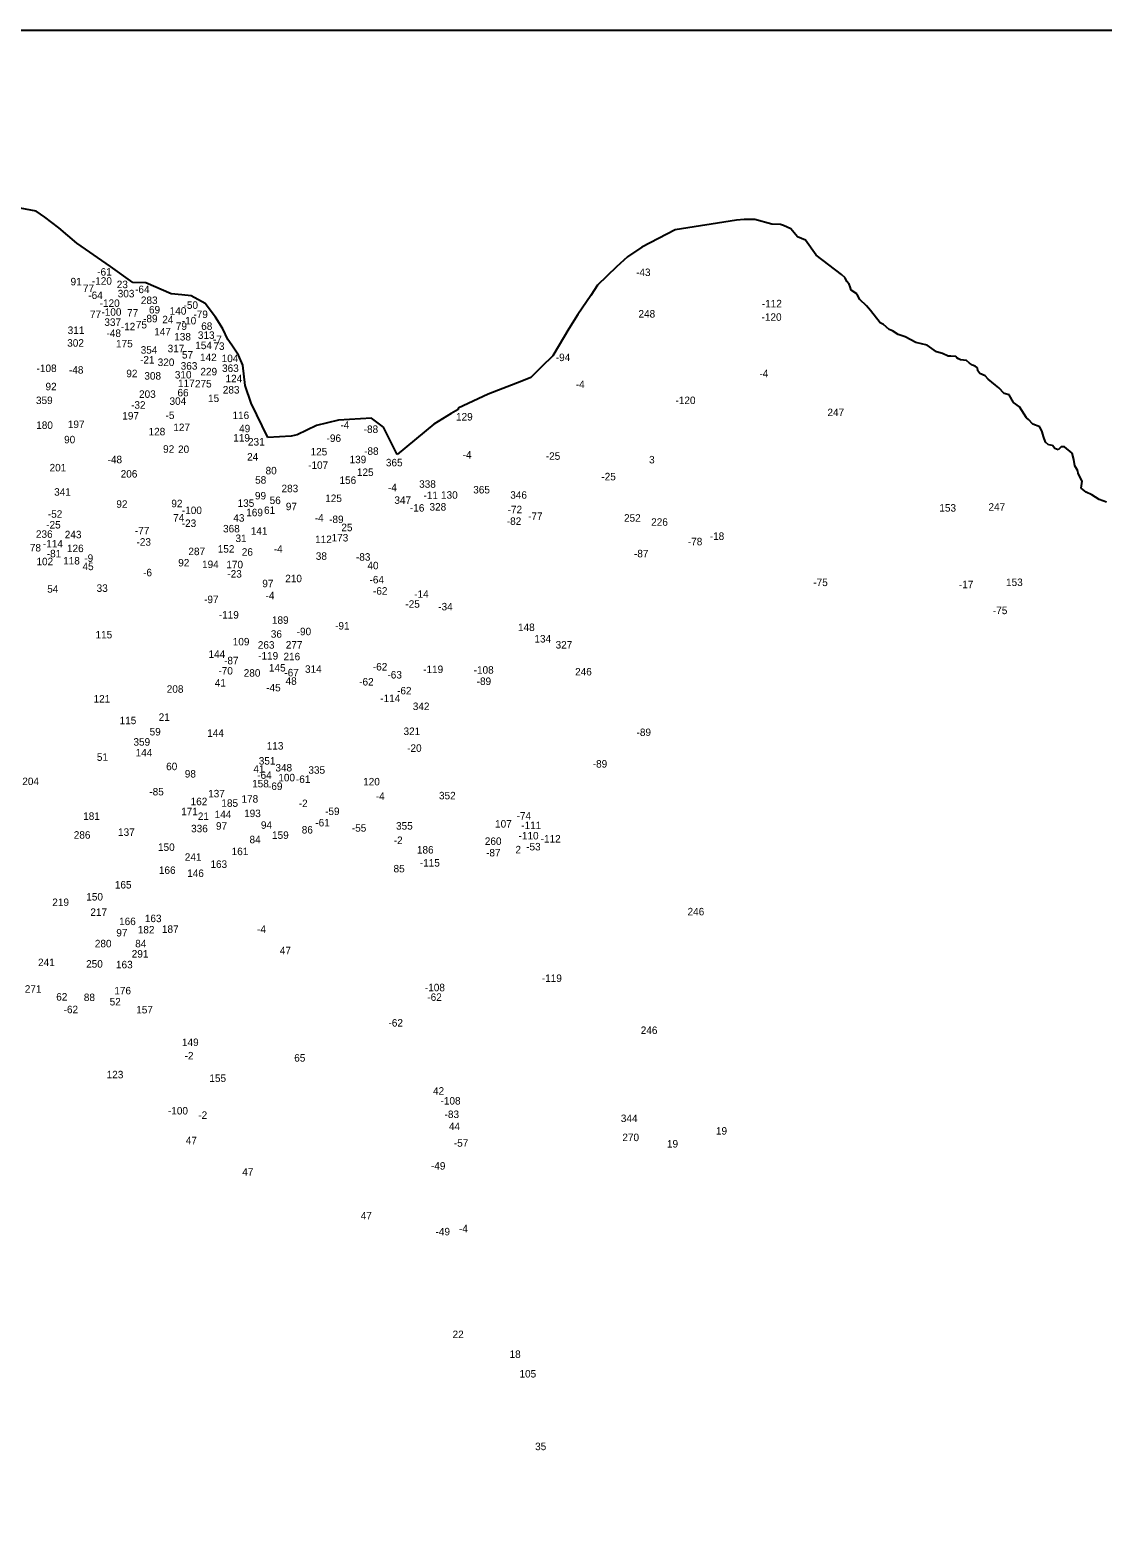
# Model space of a CAD drawing. Extents: x -780246 to -774760, y -968897 to -964868.
# Drawn here: x -778940 to -777505, y -966883 to -964868 of the extents above; entities that cross this region are included whole.
import ezdxf

# ---------------------------------------------------------------- set-up
doc = ezdxf.new("R2010")
doc.units = 0
doc.layers.add('Vrstva 13', color=7, linetype='Continuous')
doc.layers.add('Vrstva 15', color=7, linetype='Continuous')

msp = doc.modelspace()

# ---------------------------------------------------------------- linework, layer by layer
at = {"layer": 'Vrstva 13'}
for p, q in [((-778931.37, -965109.54), (-778959.99, -965104.36)), ((-778920.05, -965117.58), (-778931.37, -965109.54)), ((-778901.29, -965131.68), (-778920.05, -965117.58)), ((-777994.74, -965121.37), (-778077.17, -965134.45)), ((-777984.77, -965120.64), (-777994.74, -965121.37)), ((-777970.46, -965120.49), (-777984.77, -965120.64)), ((-777947.87, -965126.74), (-777970.46, -965120.49)), ((-778876.9, -965152.21), (-778901.29, -965131.68)), ((-778077.17, -965134.45), (-778121.63, -965157.53)), ((-777935.93, -965127.44), (-777947.87, -965126.74)), ((-777932.02, -965128.9), (-777935.93, -965127.44)), ((-777922.28, -965133.21), (-777932.02, -965128.9)), ((-777913.44, -965143.83), (-777922.28, -965133.21)), ((-778832.29, -965183.33), (-778876.9, -965152.21)), ((-778121.63, -965157.53), (-778140.83, -965170.82)), ((-777902.7, -965148.47), (-777913.44, -965143.83)), ((-777888.43, -965168.41), (-777902.7, -965148.47)), ((-778802.2, -965205.02), (-778832.29, -965183.33)), ((-778140.83, -965170.82), (-778155.55, -965183.82)), ((-777854.72, -965194.26), (-777888.43, -965168.41)), ((-778155.55, -965183.82), (-778180.7, -965208.72)), ((-777849.77, -965198.81), (-777854.72, -965194.26)), ((-777847.27, -965203.76), (-777849.77, -965198.81)), ((-777844.31, -965207.37), (-777847.27, -965203.76)), ((-778785.02, -965205.29), (-778802.2, -965205.02)), ((-778750.81, -965220.01), (-778785.02, -965205.29)), ((-778736.68, -965221.29), (-778750.81, -965220.01)), ((-778724.02, -965222.85), (-778736.68, -965221.29)), ((-778705.55, -965232.93), (-778724.02, -965222.85)), ((-778189.61, -965222.16), (-778207.13, -965247.73)), ((-778180.7, -965208.72), (-778189.61, -965222.16)), ((-777842.79, -965210.6), (-777844.31, -965207.37)), ((-777841.47, -965215.12), (-777842.79, -965210.6)), ((-777833.9, -965220.04), (-777841.47, -965215.12)), ((-777830.05, -965227.46), (-777833.9, -965220.04)), ((-778691.6, -965251.34), (-778705.55, -965232.93)), ((-777821, -965236.09), (-777830.05, -965227.46)), ((-777815.83, -965242.59), (-777821, -965236.09)), ((-777802.97, -965258.8), (-777815.83, -965242.59)), ((-778681.67, -965266.97), (-778691.6, -965251.34)), ((-778207.13, -965247.73), (-778219.21, -965266.86)), ((-777798.31, -965261.25), (-777802.97, -965258.8)), ((-777790.64, -965267.83), (-777798.31, -965261.25)), ((-778675.25, -965281.07), (-778681.67, -965266.97)), ((-778669.7, -965288.59), (-778675.25, -965281.07)), ((-778219.21, -965266.86), (-778240.53, -965303.01)), ((-777786.42, -965269.76), (-777790.64, -965267.83)), ((-777778.78, -965274.35), (-777786.42, -965269.76)), ((-777769.51, -965277.78), (-777778.78, -965274.35)), ((-777755.12, -965285.16), (-777769.51, -965277.78)), ((-778660.79, -965302.32), (-778669.7, -965288.59)), ((-778655.03, -965315.25), (-778660.79, -965302.32)), ((-778240.53, -965303.01), (-778255.82, -965317.62)), ((-777740.05, -965288.81), (-777755.12, -965285.16)), ((-777727.39, -965297.64), (-777740.05, -965288.81)), ((-777719.54, -965299.68), (-777727.39, -965297.64)), ((-777712.06, -965303.41), (-777719.54, -965299.68)), ((-777708.3, -965303.26), (-777712.06, -965303.41)), ((-777701.67, -965303.79), (-777708.3, -965303.26)), ((-777700.1, -965305.66), (-777701.67, -965303.79)), ((-778652.03, -965342.86), (-778655.03, -965315.25)), ((-778255.82, -965317.62), (-778270.13, -965331.93)), ((-777698.18, -965307.17), (-777700.1, -965305.66)), ((-777695.54, -965308.41), (-777698.18, -965307.17)), ((-777687.4, -965309.41), (-777695.54, -965308.41)), ((-777683.26, -965312.92), (-777687.4, -965309.41)), ((-777679.2, -965315.64), (-777683.26, -965312.92)), ((-777675.61, -965316.96), (-777679.2, -965315.64)), ((-777672.73, -965318.89), (-777675.61, -965316.96)), ((-777672, -965323.09), (-777672.73, -965318.89)), ((-777669.47, -965326.41), (-777672, -965323.09)), ((-778644.07, -965366.38), (-778652.03, -965342.86)), ((-778281.79, -965337.04), (-778327.17, -965354.2)), ((-778270.13, -965331.93), (-778281.79, -965337.04)), ((-777662.57, -965329.61), (-777669.47, -965326.41)), ((-777658.47, -965334.07), (-777662.57, -965329.61)), ((-777648.59, -965342.14), (-777658.47, -965334.07)), ((-777644.07, -965345.63), (-777648.59, -965342.14)), ((-778327.17, -965354.2), (-778367.26, -965373.05)), ((-777636.83, -965353.21), (-777644.07, -965345.63)), ((-777630.11, -965355.22), (-777636.83, -965353.21)), ((-777624.4, -965365.59), (-777630.11, -965355.22)), ((-778621.66, -965412.4), (-778644.07, -965366.38)), ((-778376.46, -965380.28), (-778399.58, -965394.48)), ((-778366.97, -965374.95), (-778376.46, -965380.28)), ((-778367.26, -965373.05), (-778366.97, -965374.95)), ((-777616.42, -965370.99), (-777624.4, -965365.59)), ((-777607.21, -965386.09), (-777616.42, -965370.99)), ((-778556.75, -965396.33), (-778582.67, -965408.67)), ((-778527.1, -965388.8), (-778556.75, -965396.33)), ((-778483.22, -965386.17), (-778527.1, -965388.8)), ((-778466.94, -965398.59), (-778483.22, -965386.17)), ((-778448.53, -965434.83), (-778466.94, -965398.59)), ((-778399.58, -965394.48), (-778448.53, -965434.83)), ((-777604.23, -965387.99), (-777607.21, -965386.09)), ((-777598.44, -965394.16), (-777604.23, -965387.99)), ((-777589.29, -965398.05), (-777598.44, -965394.16)), ((-777586.08, -965404.48), (-777589.29, -965398.05)), ((-777584.51, -965410.9), (-777586.08, -965404.48)), ((-778590.63, -965410.54), (-778621.66, -965412.4)), ((-778582.67, -965408.67), (-778590.63, -965410.54)), ((-777581.92, -965418.28), (-777584.51, -965410.9)), ((-777577.54, -965421.93), (-777581.92, -965418.28)), ((-777572.4, -965422.84), (-777577.54, -965421.93)), ((-777569.22, -965426.75), (-777572.4, -965422.84)), ((-777560.79, -965424.46), (-777564.77, -965428.86)), ((-777556.34, -965424.53), (-777560.79, -965424.46)), ((-777546.19, -965433.31), (-777556.34, -965424.53)), ((-777564.77, -965428.86), (-777569.22, -965426.75)), ((-777543.72, -965441.54), (-777546.19, -965433.31)), ((-777542.51, -965450.22), (-777543.72, -965441.54)), ((-777538.68, -965456.8), (-777542.51, -965450.22)), ((-777537.8, -965460.38), (-777538.68, -965456.8)), ((-777532.55, -965470.45), (-777537.8, -965460.38)), ((-777533.87, -965480), (-777532.55, -965470.45)), ((-777527.52, -965485.4), (-777533.87, -965480)), ((-777519.57, -965489.05), (-777527.52, -965485.4)), ((-777509.86, -965495.26), (-777519.57, -965489.05)), ((-777500.15, -965498.69), (-777509.86, -965495.26))]:
    msp.add_line(p, q, dxfattribs=at)
msp.add_lwpolyline([(-780246.31, -964867.52), (-774759.73, -964867.52), (-774759.73, -968897.03), (-780246.31, -968897.03)], close=True, dxfattribs=at)

# ---------------------------------------------------------------- texts
at = {"layer": 'Vrstva 15'}
for s, p in [('91', (-778885.494, -965208.7)), ('-120', (-778856.965, -965207.86)), ('-61', (-778849.858, -965195.7)), ('23', (-778823.726, -965212.51)), ('-43', (-778129.256, -965196.3)), ('77', (-778868.934, -965217.67)), ('-64', (-778861.77, -965227.05)), ('303', (-778822.416, -965224.76)), ('-64', (-778799.24, -965219.13)), ('283', (-778791.456, -965233.7)), ('77', (-778859.564, -965252.61)), ('-120', (-778846.565, -965237.6)), ('-100', (-778844.214, -965249.38)), ('77', (-778809.884, -965250.54)), ('69', (-778780.644, -965246.32)), ('140', (-778752.937, -965247.92)), ('-50', (-778734.39, -965240.15)), ('-79', (-778721.192, -965252.46)), ('248', (-778126.012, -965251.83)), ('-112', (-777961.039, -965238.14)), ('311', (-778889.346, -965273.77)), ('337', (-778840.316, -965262.93)), ('-12', (-778818.314, -965268.79)), ('75', (-778798.175, -965266.38)), ('-89', (-778788.504, -965258.17)), ('24', (-778762.822, -965259.48)), ('79', (-778744.708, -965268.38)), ('-10', (-778736.755, -965260.95)), ('68', (-778710.78, -965268.28)), ('-120', (-777961.405, -965256.15)), ('302', (-778889.976, -965290.74)), ('-48', (-778837.406, -965277.72)), ('175', (-778824.69, -965291.66)), ('147', (-778773.606, -965275.72)), ('138', (-778746.871, -965282.46)), ('154', (-778718.777, -965294.03)), ('313', (-778715.231, -965280.3)), ('-7', (-778695.049, -965285.98)), ('-21', (-778792.544, -965313.33)), ('354', (-778791.682, -965300.1)), ('317', (-778755.67, -965298.22)), ('57', (-778736.496, -965306.58)), ('142', (-778712.396, -965310.05)), ('73', (-778694.465, -965295.06)), ('104', (-778683.407, -965311.43)), ('-94', (-778236.6, -965310.04)), ('-108', (-778930.914, -965324.65)), ('-48', (-778887.606, -965326.8)), ('92', (-778810.94, -965331.58)), ('308', (-778786.816, -965334.77)), ('320', (-778768.966, -965316.57)), ('310', (-778746.051, -965333.28)), ('363', (-778738.22, -965321.45)), ('229', (-778711.85, -965329.07)), ('363', (-778682.89, -965324.52)), ('-4', (-777964.306, -965331.58)), ('92', (-778919, -965349.06)), ('117', (-778741.774, -965344.7)), ('275', (-778719.135, -965345.3)), ('283', (-778681.916, -965353.39)), ('124', (-778678.257, -965338.36)), ('-4', (-778209.866, -965346.07)), ('359', (-778931.77, -965367.48)), ('-32', (-778804.58, -965373.68)), ('203', (-778793.906, -965359.16)), ('304', (-778753.182, -965368.52)), ('66', (-778742.514, -965357.23)), ('15', (-778701.631, -965364.8)), ('-120', (-778076.515, -965367.48)), ('197', (-778816.303, -965388.13)), ('-5', (-778758.45, -965387.45)), ('116', (-778668.939, -965387.54)), ('129', (-778370.004, -965389.46)), ('247', (-777873.291, -965383.62)), ('180', (-778931.411, -965400.71)), ('197', (-778889.133, -965399.55)), ('128', (-778781.201, -965409.28)), ('127', (-778748.06, -965403.59)), ('49', (-778660.076, -965405.2)), ('-4', (-778524.616, -965400.51)), ('-88', (-778493.5, -965406.08)), ('90', (-778894.12, -965419.95)), ('92', (-778761.74, -965432.55)), ('20', (-778741.776, -965432.96)), ('119', (-778667.969, -965417.64)), ('231', (-778648.231, -965422.92)), ('-96', (-778543.107, -965418.09)), ('-88', (-778492.91, -965435.38)), ('-48', (-778835.946, -965446.62)), ('24', (-778649.382, -965442.99)), ('-107', (-778567.794, -965454.13)), ('125', (-778564.551, -965436.15)), ('139', (-778512.404, -965446.61)), ('365', (-778463.78, -965450.71)), ('-4', (-778361.186, -965440.36)), ('-25', (-778249.93, -965442.01)), ('3', (-778111.816, -965446.84)), ('201', (-778913.56, -965457.49)), ('206', (-778818.46, -965465.79)), ('58', (-778638.686, -965473.95)), ('80', (-778624.686, -965461.45)), ('156', (-778525.854, -965474.25)), ('125', (-778502.561, -965463.64)), ('-25', (-778175.66, -965469.45)), ('341', (-778907.406, -965489.98)), ('99', (-778638.934, -965494.99)), ('283', (-778603.376, -965485.36)), ('-4', (-778461.056, -965484.01)), ('338', (-778419.336, -965479.41)), ('-11', (-778413.479, -965494.46)), ('130', (-778390.081, -965494.05)), ('365', (-778346.99, -965487.02)), ('346', (-778297.466, -965494.05)), ('92', (-778824.27, -965506.15)), ('92', (-778750.71, -965505.46)), ('-100', (-778736.634, -965514.53)), ('135', (-778662.121, -965504.92)), ('61', (-778626.754, -965514.44)), ('56', (-778619.26, -965501.21)), ('97', (-778597.598, -965509.43)), ('125', (-778544.961, -965498.46)), ('347', (-778452.471, -965500.93)), ('-16', (-778431.638, -965511.26)), ('328', (-778405.476, -965509.94)), ('-72', (-778300.968, -965513.51)), ('153', (-777723.661, -965511.3)), ('247', (-777657.971, -965510.06)), ('-25', (-778918.06, -965533.88)), ('-52', (-778915.86, -965519.49)), ('74', (-778748.301, -965524.54)), ('-23', (-778736.81, -965531.82)), ('43', (-778667.812, -965524.74)), ('169', (-778650.598, -965517.47)), ('-4', (-778558.936, -965524.69)), ('-89', (-778539.734, -965526.6)), ('-82', (-778302.1, -965529.05)), ('-77', (-778273.618, -965522.3)), ('252', (-778145.376, -965524.78)), ('226', (-778109.02, -965530.19)), ('236', (-778931.8, -965546.31)), ('243', (-778893.242, -965546.94)), ('-77', (-778799.438, -965541.67)), ('368', (-778681.55, -965539.08)), ('31', (-778664.971, -965551.96)), ('141', (-778644.491, -965542.15)), ('112', (-778558.476, -965553.36)), ('173', (-778536.43, -965551.21)), ('25', (-778523.356, -965537.49)), ('-78', (-778059.978, -965556.3)), ('-18', (-778030.674, -965549.12)), ('78', (-778939.965, -965564.6)), ('-114', (-778922.495, -965559.26)), ('-81', (-778917.314, -965572.41)), ('126', (-778890.314, -965565.49)), ('-23', (-778797.31, -965556.83)), ('287', (-778727.926, -965569.51)), ('152', (-778688.671, -965566.15)), ('26', (-778656.51, -965570.23)), ('-4', (-778613.776, -965566.29)), ('38', (-778557.516, -965575.74)), ('-83', (-778503.84, -965576.9)), ('-87', (-778132.029, -965572.41)), ('102', (-778931.13, -965583.01)), ('118', (-778895.426, -965582)), ('45', (-778869.502, -965589.56)), ('-9', (-778867.094, -965578.46)), ('92', (-778741.51, -965584.58)), ('194', (-778709.63, -965586.77)), ('170', (-778677.15, -965587.06)), ('40', (-778488.502, -965588.39)), ('-6', (-778788.494, -965597.72)), ('-23', (-778675.82, -965599.52)), ('97', (-778629.088, -965612.44)), ('210', (-778598.391, -965605.75)), ('-64', (-778485.67, -965607.23)), ('-75', (-777892.228, -965610.9)), ('-17', (-777697.524, -965613.69)), ('153', (-777634.471, -965610.78)), ('54', (-778916.722, -965619.7)), ('33', (-778850.666, -965618.59)), ('-97', (-778706.962, -965633.65)), ('-4', (-778624.746, -965628.46)), ('-62', (-778481.044, -965622.32)), ('-14', (-778425.99, -965626.57)), ('-119', (-778687.233, -965654.31)), ('-25', (-778437.74, -965639.83)), ('-34', (-778393.776, -965643.35)), ('-75', (-777652.018, -965648.41)), ('189', (-778616.194, -965661.32)), ('-90', (-778583.064, -965676.6)), ('-91', (-778531.728, -965668.98)), ('148', (-778287.116, -965670.96)), ('115', (-778852.106, -965680.81)), ('109', (-778668.604, -965690.17)), ('263', (-778635.09, -965694.54)), ('36', (-778617.71, -965679.93)), ('277', (-778597.664, -965694.39)), ('134', (-778265.187, -965686.31)), ('327', (-778236.826, -965694.35)), ('144', (-778701.062, -965706.85)), ('-87', (-778680.209, -965715.43)), ('-119', (-778634.603, -965709.13)), ('216', (-778600.744, -965710.05)), ('-70', (-778687.779, -965729.12)), ('280', (-778653.946, -965731.99)), ('145', (-778620.176, -965725.1)), ('-67', (-778599.562, -965731.54)), ('314', (-778571.967, -965726.81)), ('-62', (-778481.214, -965723.76)), ('-63', (-778461.734, -965734.45)), ('-119', (-778413.943, -965727.13)), ('-108', (-778346.434, -965728.01)), ('246', (-778210.746, -965730.36)), ('208', (-778756.836, -965753.5)), ('41', (-778692.556, -965745.28)), ('-45', (-778623.866, -965751.62)), ('48', (-778597.952, -965742.86)), ('-62', (-778499.504, -965743.83)), ('-62', (-778448.844, -965755.69)), ('-89', (-778342.374, -965743.09)), ('121', (-778854.726, -965766.53)), ('-114', (-778471.355, -965765.88)), ('342', (-778427.832, -965776.61)), ('115', (-778819.926, -965795.5)), ('21', (-778767.661, -965791.11)), ('59', (-778779.77, -965810.59)), ('144', (-778702.822, -965812.45)), ('321', (-778440.221, -965809.98)), ('-89', (-778128.584, -965811.36)), ('359', (-778801.39, -965824.24)), ('144', (-778798.442, -965838.49)), ('113', (-778623.126, -965829.49)), ('-20', (-778435.36, -965832.5)), ('51', (-778850.321, -965844.52)), ('60', (-778757.66, -965857.04)), ('351', (-778633.791, -965849.55)), ('348', (-778611.542, -965858.73)), ('-89', (-778187.164, -965853.55)), ('204', (-778950.042, -965876.95)), ('98', (-778732.76, -965866.87)), ('41', (-778641.006, -965860.41)), ('-64', (-778635.86, -965868.65)), ('100', (-778607.661, -965871.91)), ('-61', (-778584.118, -965874.06)), ('335', (-778567.476, -965861.79)), ('120', (-778494.221, -965877.35)), ('-85', (-778780.16, -965890.77)), ('137', (-778701.51, -965893.34)), ('158', (-778642.701, -965879.96)), ('-69', (-778621.467, -965883.45)), ('-4', (-778477.316, -965896.76)), ('352', (-778392.816, -965896.01)), ('171', (-778737.664, -965917.34)), ('162', (-778724.924, -965903.87)), ('185', (-778683.811, -965906.03)), ('178', (-778656.9, -965900.44)), ('-2', (-778580.35, -965906.36)), ('-59', (-778545.124, -965916.99)), ('181', (-778868.636, -965923.46)), ('21', (-778715.321, -965923.61)), ('144', (-778692.732, -965920.99)), ('97', (-778691.018, -965936.61)), ('193', (-778653.414, -965919.75)), ('94', (-778630.936, -965935.4)), ('-61', (-778558.188, -965932.22)), ('-55', (-778509.34, -965939.25)), ('355', (-778450.246, -965936.49)), ('107', (-778317.8, -965933.77)), ('-74', (-778288.954, -965922.98)), ('-111', (-778282.784, -965935.73)), ('286', (-778881.21, -965948.62)), ('137', (-778821.98, -965944.82)), ('336', (-778724.31, -965940.03)), ('84', (-778646.132, -965954.72)), ('159', (-778616.054, -965948.86)), ('86', (-778576.32, -965941.72)), ('-2', (-778453.32, -965955.73)), ('260', (-778331.5, -965956.94)), ('-110', (-778286.37, -965949.65)), ('-112', (-778256.829, -965953.74)), ('150', (-778768.571, -965964.93)), ('241', (-778732.726, -965978.19)), ('161', (-778670.088, -965970.66)), ('186', (-778422.314, -965968.47)), ('-87', (-778329.849, -965972.35)), ('2', (-778290.576, -965968.23)), ('-53', (-778276.22, -965964.29)), ('166', (-778767.368, -965995.72)), ('146', (-778729.53, -965999.82)), ('163', (-778698.434, -965987.67)), ('85', (-778453.566, -965993.7)), ('-115', (-778418.419, -965985.91)), ('165', (-778826.274, -966015.25)), ('219', (-778909.904, -966038.65)), ('150', (-778864.481, -966031.34)), ('217', (-778859, -966051.82)), ('163', (-778786.164, -966060.22)), ('246', (-778060.376, -966051.13)), ('97', (-778824.328, -966079.38)), ('166', (-778820.598, -966064.17)), ('182', (-778795.611, -966075.28)), ('187', (-778763.33, -966074.55)), ('-4', (-778636.106, -966074.61)), ('280', (-778853.036, -966093.88)), ('84', (-778799.012, -966093.87)), ('241', (-778929.006, -966119.03)), ('250', (-778864.686, -966121.05)), ('291', (-778803.704, -966107.6)), ('47', (-778605.631, -966103.17)), ('163', (-778824.764, -966121.95)), ('-119', (-778255.263, -966140.18)), ('271', (-778946.71, -966154.56)), ('176', (-778826.963, -966156.8)), ('-108', (-778411.644, -966152.62)), ('62', (-778904.66, -966165.11)), ('88', (-778867.746, -966165.74)), ('52', (-778833.226, -966171.6)), ('-62', (-778408.394, -966165.5)), ('-62', (-778894.774, -966181.99)), ('157', (-778797.66, -966182.26)), ('-62', (-778460.314, -966199.85)), ('246', (-778122.986, -966209.75)), ('149', (-778736.5, -966225.85)), ('-2', (-778732.97, -966243.73)), ('65', (-778586.4, -966246.71)), ('123', (-778837.231, -966269.03)), ('155', (-778699.861, -966273.91)), ('42', (-778400.772, -966290.9)), ('-100', (-778755.244, -966317.41)), ('-108', (-778390.724, -966304.13)), ('-83', (-778385.31, -966322.13)), ('-2', (-778714.69, -966323.27)), ('44', (-778379.468, -966338.18)), ('344', (-778149.618, -966327.54)), ('47', (-778731.371, -966357.1)), ('-57', (-778372.949, -966360.52)), ('270', (-778147.545, -966353.01)), ('19', (-778087.904, -966361.59)), ('19', (-778022.404, -966344.33)), ('47', (-778655.921, -966399.23)), ('-49', (-778403.53, -966391.13)), ('47', (-778497.431, -966457.74)), ('-49', (-778397.4, -966478.97)), ('-4', (-778366.066, -966474.91)), ('22', (-778374.646, -966616.38)), ('18', (-778298.401, -966642.93)), ('105', (-778285.15, -966669.13)), ('35', (-778264.236, -966766.24))]:
    msp.add_text(s, height=10, dxfattribs=at).set_placement(p)

doc.saveas('drawing.dxf')
